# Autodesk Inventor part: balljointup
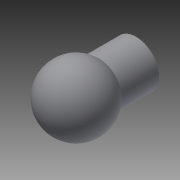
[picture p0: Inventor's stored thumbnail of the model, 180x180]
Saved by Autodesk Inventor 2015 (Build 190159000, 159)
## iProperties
Created: 2015-02
Part Number: balljointup
Material: Generic
Document SubType Name: Modeling
Designer: sungeun
Density: 1 g/cm^3
Appearance: Default
Author: sungeun
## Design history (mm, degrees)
sketch "Sketch1"
  geometry: L1 (-5, 4.899)-(-5, 13); L2 (-5, 13)-(0, 13); L3 (0, 13)-(0, -7); A1 r 7 centre (0, 0) between (-5, 4.899) and (0, -7); 2 further points
  constraints: 6 end point, 2 coincident, 2 point on circle, 1 centre point, 1 parallel, 1 perpendicular, 1 vertical, 1 vertical alignment
  dimensions: "d0" = 14 diameter of A1; "d4" = 5 distance of L1.end L2.end; "d5" = 20 distance of L2.end L3.end
revolve "Revolution1" sketch "Sketch1" stored, may be unused: angle "d6" = 90 deg
body "Solid1"
